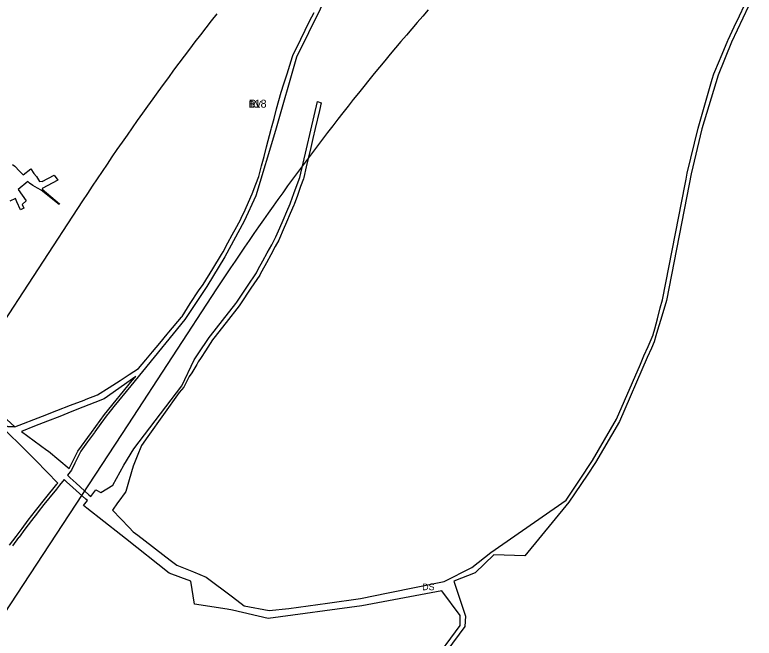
# Model space of a CAD drawing. Extents: x -537034 to -534353, y -1176562 to -1173176.
# Drawn here: x -535284 to -534730, y -1175788 to -1175321 of the extents above; entities that cross this region are included whole.
import ezdxf

# ---------------------------------------------------------------- set-up
doc = ezdxf.new("R2010")
doc.units = 0
for name, color, linetype in [('90320013', 7, 'Continuous'), ('90350033', 7, 'Continuous'), ('90450013', 7, 'Continuous'), ('ID_rezerva', 7, 'Continuous'), ('ID_rezervaR', 7, 'Continuous')]:
    doc.layers.add(name, color=color, linetype=linetype)

msp = doc.modelspace()

# ---------------------------------------------------------------- linework, layer by layer
at = {"layer": '90320013'}
for points in [[(-535046.44, -1175297.98), (-535073.18, -1175352.43), (-535089.06, -1175407.38), (-535103.65, -1175456.2), (-535112.4, -1175475.25), (-535126.93, -1175501.89), (-535140.56, -1175524.19), (-535157.02, -1175548.97), (-535188.81, -1175587.99), (-535197.55, -1175598.71), (-535210.21, -1175614.22), (-535214.81, -1175619.86), (-535215.3, -1175620.47), (-535219.88, -1175626.78), (-535224.53, -1175633.18), (-535224.85, -1175633.62), (-535229.99, -1175640.7), (-535234.95, -1175647.52), (-535235.18, -1175647.99), (-535239.38, -1175656.52), (-535242.02, -1175661.86), (-535245.05, -1175665.69), (-535242.98, -1175667.66), (-535238.5, -1175671.68), (-535228.86, -1175680.34), (-535227.6, -1175681.48), (-535223.72, -1175676.61), (-535220.03, -1175678.6), (-535210.95, -1175673.05), (-535202.74, -1175658.11), (-535195.2, -1175645.89), (-535159.16, -1175598.64), (-535150.01, -1175579.1), (-535146.93, -1175574.59), (-535138.67, -1175562.51), (-535137.73, -1175561.3), (-535128.68, -1175549.71), (-535118.65, -1175536.85), (-535117.97, -1175535.84), (-535110.04, -1175524.01), (-535103.35, -1175514.04), (-535103.09, -1175513.57), (-535101.89, -1175511.35), (-535098.45, -1175505.03), (-535095.22, -1175499.11), (-535091.84, -1175492.9), (-535089.24, -1175488.11), (-535088.72, -1175486.92), (-535085.87, -1175480.35), (-535083.38, -1175474.6), (-535080.57, -1175468.1), (-535078.08, -1175462.35), (-535077.75, -1175461.45), (-535075.28, -1175454.63), (-535072.82, -1175447.85), (-535070.86, -1175442.43), (-535057.52, -1175385.55), (-535054.7, -1175386.57), (-535056.07, -1175392.43), (-535059.21, -1175405.79), (-535060.96, -1175413.24), (-535062.58, -1175420.14), (-535065.99, -1175434.65), (-535067.86, -1175442.64), (-535068.05, -1175443.45), (-535070.16, -1175449.26), (-535072.61, -1175456.03), (-535075.07, -1175462.83), (-535075.27, -1175463.37), (-535077.92, -1175469.5), (-535080.73, -1175475.98), (-535083.23, -1175481.75), (-535086.08, -1175488.33), (-535086.6, -1175489.54), (-535089.2, -1175494.3), (-535092.59, -1175500.51), (-535095.81, -1175506.41), (-535099.24, -1175512.71), (-535100.46, -1175514.95), (-535100.87, -1175515.7), (-535107.39, -1175525.43), (-535115.3, -1175537.22), (-535116.29, -1175538.7), (-535125.97, -1175551.1), (-535135.2, -1175562.92), (-535136.2, -1175564.2), (-535141.58, -1175572.48), (-535144.78, -1175577.4), (-535146.96, -1175580.76), (-535147.25, -1175581.25), (-535148.03, -1175582.59), (-535151.68, -1175588.84), (-535153.68, -1175591.72), (-535157.66, -1175599.74), (-535161.24, -1175603.76), (-535184.81, -1175636.58), (-535189.46, -1175643.28), (-535192.81, -1175651.42), (-535195.86, -1175658.84), (-535198.75, -1175669.05), (-535201.26, -1175677.9), (-535201.68, -1175678.47), (-535206.57, -1175685.11), (-535207.51, -1175686.45), (-535211.34, -1175691.91), (-535198.63, -1175704.88), (-535195.8, -1175707.99), (-535192.29, -1175710.66), (-535167.89, -1175729.26), (-535162.92, -1175733.05), (-535150.4, -1175738.16), (-535141.07, -1175741.96), (-535121.28, -1175756.78), (-535112.39, -1175763.44), (-535093.81, -1175767.01), (-535079.13, -1175765.46), (-535050.13, -1175761.47), (-535025.18, -1175758.03), (-535004.49, -1175753.79), (-534962.54, -1175745.2), (-534941.75, -1175734.73), (-534927.5, -1175723.52), (-534871.16, -1175684.32), (-534861.07, -1175669.23), (-534851.31, -1175654.61), (-534833.4, -1175623.66), (-534815.36, -1175582.32), (-534812.7, -1175576.21), (-534809.62, -1175569.15), (-534805.85, -1175560.51), (-534805.77, -1175560.19), (-534804.64, -1175555.94), (-534802.64, -1175548.39), (-534800.49, -1175540.25), (-534798.91, -1175534.27), (-534781.84, -1175447.55), (-534781.16, -1175443.84), (-534780.35, -1175439.37), (-534772.14, -1175405.55), (-534761.56, -1175368.72), (-534760.44, -1175364.83), (-534759.7, -1175363.09), (-534754.16, -1175349.99), (-534749.9, -1175339.92), (-534749.6, -1175339.29), (-534745.08, -1175329.69), (-534741.19, -1175321.42), (-534737.42, -1175313.42)], [(-534730.05, -1175304.93), (-534747.12, -1175341.05), (-534757.17, -1175365.82), (-534769.45, -1175406.16), (-534777.26, -1175439.82), (-534778.75, -1175447.45), (-534795.78, -1175534.7), (-534797.85, -1175541.56), (-534800.28, -1175549.58), (-534802.53, -1175557.01), (-534803.79, -1175561.2), (-534805.18, -1175565.8), (-534807.17, -1175570.39), (-534810.23, -1175577.44), (-534831.04, -1175625.41), (-534848.96, -1175656.17), (-534855.33, -1175665.63), (-534868.94, -1175685.87), (-534902.05, -1175726.08), (-534925.24, -1175725.42), (-534939.36, -1175738.75), (-534955.25, -1175745.12), (-534953.52, -1175750.32), (-534951.76, -1175755.6), (-534946.52, -1175771.33), (-534947.07, -1175779.02), (-534969.88, -1175809.65)], [(-535295.21, -1175628.81), (-535284.44, -1175629.29), (-535263.82, -1175621.35), (-535253.07, -1175617.21), (-535242.74, -1175613.24), (-535232.44, -1175609.28), (-535230.95, -1175608.71), (-535222.6, -1175605.49), (-535213.79, -1175599.86), (-535205.56, -1175594.61), (-535198.7, -1175590.23), (-535191.7, -1175585.77), (-535186.17, -1175579.15), (-535181.13, -1175573.11), (-535175.7, -1175566.61), (-535170.17, -1175559.99), (-535168.98, -1175558.56), (-535159.43, -1175547.12), (-535159.09, -1175546.59), (-535152.94, -1175537), (-535146.84, -1175527.49), (-535143.17, -1175522.62), (-535135.96, -1175510.86), (-535129.49, -1175500.32), (-535128.36, -1175498.25), (-535124.69, -1175491.52), (-535121.39, -1175485.47), (-535117.96, -1175479.18), (-535115.02, -1175473.77), (-535114.68, -1175473.01), (-535111.87, -1175466.75), (-535109.28, -1175460.96), (-535106.52, -1175454.81), (-535106.48, -1175454.72), (-535103.71, -1175447.53), (-535101.51, -1175441.83), (-535101.22, -1175440.74), (-535099.43, -1175433.9), (-535097.55, -1175426.71), (-535095.64, -1175419.43), (-535092.23, -1175406.41), (-535091.94, -1175405.34), (-535090.09, -1175398.4), (-535088.14, -1175391.1), (-535084.77, -1175378.46), (-535082.78, -1175372.28), (-535080.36, -1175364.76), (-535078.28, -1175358.28), (-535076.19, -1175351.77), (-535075.96, -1175351.06), (-535070.02, -1175338.97), (-535063.39, -1175325.47), (-535060.09, -1175318.76)], [(-535288.41, -1175718.1), (-535283.55, -1175711.47), (-535279.07, -1175705.67), (-535274.35, -1175699.26), (-535269.07, -1175692.43), (-535261.11, -1175682.71), (-535252.87, -1175672.38), (-535252.69, -1175672.14), (-535252.29, -1175671.63), (-535268.8, -1175654.55), (-535277.83, -1175645.64), (-535292.07, -1175631.59)], [(-534972.28, -1175807.68), (-534950.61, -1175778.33), (-534950.51, -1175770.73), (-534964.16, -1175752.21), (-535024.33, -1175763.57), (-535094.47, -1175772.94), (-535121.13, -1175766.75), (-535125.27, -1175766.1), (-535149.83, -1175762.25), (-535152.61, -1175745.06), (-535159.9, -1175742.34), (-535168.68, -1175739.06), (-535201.51, -1175713.09), (-535204.96, -1175710.36), (-535230.41, -1175690.23), (-535232.96, -1175688.21), (-535230.05, -1175684.56), (-535231.26, -1175683.48), (-535240.91, -1175674.8), (-535245.6, -1175670.57), (-535247.58, -1175668.91), (-535250.88, -1175673.09), (-535253.34, -1175676.14), (-535257.99, -1175681.89), (-535259.12, -1175683.3), (-535262.63, -1175687.65), (-535266.92, -1175692.96), (-535267.58, -1175693.78), (-535272.03, -1175699.66), (-535276.9, -1175706.1), (-535281.34, -1175711.96), (-535281.64, -1175712.35), (-535286.29, -1175718.5)]]:
    msp.add_lwpolyline(points, dxfattribs=at)
msp.add_lwpolyline([(-535227.09, -1175633.62), (-535217.13, -1175620.02), (-535196.41, -1175594.7), (-535193.82, -1175591.54), (-535217.5, -1175608.32), (-535224.55, -1175611.11), (-535233.53, -1175614.66), (-535241.73, -1175617.91), (-535250.84, -1175621.52), (-535259.91, -1175625.11), (-535269.63, -1175628.96), (-535279.53, -1175632.88), (-535260.36, -1175646.8), (-535259.3, -1175647.57), (-535243.62, -1175660.53), (-535237.35, -1175647.63)], close=True, dxfattribs=at)
at = {"layer": '90350033'}
for points in [[(-534974.51, -1175316.79), (-534978.62, -1175321.51), (-534982.73, -1175326.26), (-534986.82, -1175331), (-534990.88, -1175335.78), (-534994.93, -1175340.56), (-534998.97, -1175345.35), (-535002.99, -1175350.16), (-535006.99, -1175354.98), (-535010.97, -1175359.81), (-535014.95, -1175364.65), (-535018.9, -1175369.51), (-535022.84, -1175374.38), (-535026.76, -1175379.26), (-535030.67, -1175384.16), (-535034.56, -1175389.07), (-535038.43, -1175393.99), (-535042.29, -1175398.92), (-535046.12, -1175403.86), (-535049.95, -1175408.82), (-535053.75, -1175413.78), (-535057.54, -1175418.76), (-535061.31, -1175423.75), (-535065.06, -1175428.75), (-535068.8, -1175433.77), (-535072.52, -1175438.79), (-535076.23, -1175443.83), (-535079.91, -1175448.87), (-535083.57, -1175453.93), (-535087.22, -1175459), (-535090.86, -1175464.08), (-535094.48, -1175469.18), (-535098.07, -1175474.28), (-535101.65, -1175479.39), (-535105.22, -1175484.52), (-535108.76, -1175489.65), (-535112.29, -1175494.79), (-535115.8, -1175499.95), (-535119.29, -1175505.11), (-535122.76, -1175510.29), (-535126.22, -1175515.47), (-535129.66, -1175520.67), (-535133.13, -1175525.94), (-535199.83, -1175627.8), (-535772.63, -1176500.85)], [(-535300.19, -1175562.02), (-535233.47, -1175460.12), (-535229.84, -1175454.6), (-535226.18, -1175449.08), (-535222.51, -1175443.57), (-535218.81, -1175438.06), (-535215.1, -1175432.57), (-535211.37, -1175427.09), (-535207.62, -1175421.62), (-535203.85, -1175416.16), (-535200.06, -1175410.72), (-535196.25, -1175405.28), (-535192.43, -1175399.86), (-535188.58, -1175394.44), (-535184.72, -1175389.04), (-535180.84, -1175383.65), (-535176.94, -1175378.27), (-535173.02, -1175372.91), (-535169.09, -1175367.55), (-535165.13, -1175362.21), (-535161.16, -1175356.88), (-535157.17, -1175351.56), (-535153.16, -1175346.26), (-535149.13, -1175340.97), (-535145.09, -1175335.68), (-535141.02, -1175330.42), (-535136.94, -1175325.16), (-535132.84, -1175319.92)]]:
    msp.add_lwpolyline(points, dxfattribs=at)
at = {"layer": '90450013'}
for points in [[(-535286.25, -1175432.68), (-535284.39, -1175434.07), (-535280.87, -1175437.74), (-535278.24, -1175440.46), (-535272.5, -1175436.13), (-535270.19, -1175439.41), (-535268.12, -1175441.85), (-535265.91, -1175445.49), (-535264.06, -1175445.24), (-535263.88, -1175445.48), (-535254.87, -1175440.66), (-535252.27, -1175444.54), (-535263.98, -1175450.86), (-535263.71, -1175451.19), (-535263.94, -1175451.33), (-535251.01, -1175462.37), (-535251.27, -1175462.7), (-535257.16, -1175458.13), (-535264.81, -1175451.97), (-535267.46, -1175450.55), (-535271.09, -1175448.41), (-535273.45, -1175446.84), (-535274.61, -1175445.56), (-535281.99, -1175451.4), (-535276.04, -1175460.12), (-535278.98, -1175462.81), (-535277.6, -1175465.41), (-535280.1, -1175466.7), (-535282.93, -1175460.66), (-535284.02, -1175458.34), (-535288.28, -1175460.19)], [(-535343.16, -1175575.62), (-535284.44, -1175629.29), (-535295.21, -1175628.81)]]:
    msp.add_lwpolyline(points, dxfattribs=at)

# ---------------------------------------------------------------- texts
at = {"layer": '90320013'}
msp.add_text('DS', height=5, rotation=0, dxfattribs=at).set_placement((-534979.03, -1175751.8))
at = {"layer": '90350033'}
msp.add_text('DV', height=5, dxfattribs=at).set_placement((-535109.11, -1175390.21))
at = {"layer": 'ID_rezerva'}
msp.add_text('118', height=6, rotation=0, dxfattribs=at).set_placement((-535109.11, -1175390.21))
at = {"layer": 'ID_rezervaR'}
msp.add_text('R', height=6, rotation=0, dxfattribs=at).set_placement((-535109.11, -1175390.21))

doc.saveas('drawing.dxf')
